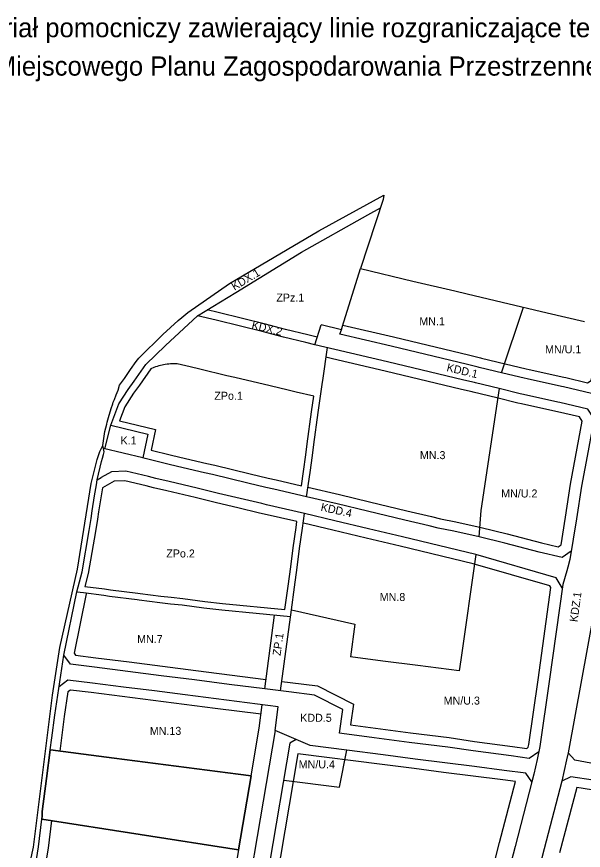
# Model space of a CAD drawing. Extents: x 7416945 to 7418410, y 5548550 to 5549803.
# Drawn here: x 7417259 to 7417613, y 5549282 to 5549803 of the extents above; entities that cross this region are included whole.
import ezdxf

# ---------------------------------------------------------------- set-up
doc = ezdxf.new("R2010")
doc.units = 0
for name, color, linetype in [('info', 7, 'Continuous'), ('linie rozgraniczające', 7, 'Continuous'), ('nieprzekraczalna linia lokalizacyjna', 7, 'Continuous'), ('nieprzekraczalne linie zabudowy', 7, 'Continuous'), ('przeznaczenia terenów', 7, 'Continuous'), ('wyrok sądu', 7, 'Continuous')]:
    doc.layers.add(name, color=color, linetype=linetype)

msp = doc.modelspace()

# ---------------------------------------------------------------- linework, layer by layer
at = {"layer": 'linie rozgraniczające'}
for p, q in [((7417562.21, 5549580.39), (7417575.91, 5549621.36)), ((7417430.79, 5549432.26), (7417470.53, 5549423.27)), ((7417460.95, 5549321.35), (7417465.4, 5549344.5)), ((7417397.8, 5549282.3), (7417274.82, 5549301.52))]:
    msp.add_line(p, q, dxfattribs=at)
for points in [[(7417265.78, 5549266.8), (7417269.56, 5549284.01), (7417281.43, 5549378.96), (7417286.09, 5549408.66), (7417297.04, 5549457.57), (7417305.73, 5549511.21), (7417309.41, 5549526.27), (7417310.95, 5549531.1), (7417312.91, 5549534.86), (7417314.25, 5549543.78), (7417315.36, 5549548.22), (7417315.7, 5549549.58), (7417316.52, 5549552.39), (7417318.21, 5549558.03), (7417319.09, 5549560.93), (7417319.48, 5549561.95), (7417320.14, 5549563.73), (7417321.28, 5549566.59), (7417322.44, 5549569.46), (7417323.3, 5549572.65), (7417326.48, 5549576.82), (7417326.92, 5549577.4), (7417328.51, 5549579.88), (7417330.15, 5549582.39), (7417333.79, 5549587.38), (7417335.36, 5549589.45), (7417340.1, 5549594.15), (7417345.97, 5549599.85), (7417346.5, 5549600.36), (7417350.44, 5549604.33), (7417359.93, 5549613.06), (7417362.31, 5549614.95), (7417366.04, 5549617.94), (7417392.12, 5549636.23), (7417447.88, 5549669.14), (7417488.65, 5549691.32), (7417488.23, 5549688.73), (7417473.96, 5549645.47), (7417506.75, 5549637.72), (7417506.75, 5549637.72), (7417533.04, 5549631.5), (7417540.76, 5549629.67), (7417562.48, 5549624.53), (7417590.76, 5549617.84), (7417614.12, 5549612.32)], [(7417314.25, 5549532.81), (7417317.93, 5549547.59), (7417323, 5549560.99), (7417328.79, 5549569.95), (7417332.54, 5549575.05), (7417339.88, 5549585.49), (7417352.08, 5549597.47), (7417372.07, 5549616.05), (7417396.1, 5549630.57), (7417437.07, 5549655.8), (7417478.59, 5549679.02), (7417486.4, 5549683.36), (7417486.46, 5549683.37)], [(7417462.02, 5549607.14), (7417462.8, 5549609.42), (7417473.96, 5549645.47)], [(7417446.94, 5549602.62), (7417441.05, 5549604.07), (7417427.15, 5549607.51), (7417413.7, 5549610.97), (7417400.22, 5549614.35), (7417384.97, 5549618.11), (7417378.17, 5549619.73)], [(7417445.43, 5549597.84), (7417439.85, 5549599.22), (7417425.93, 5549602.66), (7417412.47, 5549606.12), (7417399.01, 5549609.5), (7417383.79, 5549613.25), (7417372.07, 5549616.05)], [(7417619.99, 5549551.6), (7417616.03, 5549557.7), (7417598.58, 5549561.83), (7417597.44, 5549562.11), (7417575.89, 5549566.8), (7417573.85, 5549567.3), (7417560.72, 5549570.46), (7417545.86, 5549574.04), (7417545.19, 5549574.21), (7417538.59, 5549575.77), (7417490.83, 5549587.31), (7417457.88, 5549595), (7417445.43, 5549597.84), (7417449.35, 5549610.27)], [(7417624.4, 5549571.14), (7417618.37, 5549567.42), (7417600.92, 5549571.55), (7417599.7, 5549571.85), (7417578.14, 5549576.54), (7417576.21, 5549577.02), (7417563.06, 5549580.18), (7417548.26, 5549583.75), (7417547.57, 5549583.92), (7417540.91, 5549585.5), (7417493.14, 5549597.04), (7417461.13, 5549604.52), (7417462.02, 5549607.14), (7417449.35, 5549610.27)], [(7417633.2, 5549607.8), (7417620.9, 5549556.55), (7417616.31, 5549531.69), (7417612.22, 5549509.52), (7417608.98, 5549489.09), (7417604.95, 5549463.66), (7417603.56, 5549458.92), (7417602.9, 5549456.68), (7417600.38, 5549448.11)], [(7417652.74, 5549603.16), (7417639.38, 5549551.6), (7417635.56, 5549527.28), (7417631.94, 5549504.23), (7417628.25, 5549481.74), (7417626.38, 5549470.4), (7417624.29, 5549457.71), (7417624.07, 5549456.36), (7417624.04, 5549453.54), (7417603.72, 5549342.84), (7417602.77, 5549338.52), (7417599.85, 5549325.25), (7417588.8, 5549282.89), (7417582.37, 5549257.96)], [(7417453.1, 5549596.09), (7417450.22, 5549575.53), (7417450.07, 5549574.49), (7417447.41, 5549555.47), (7417444.62, 5549535.51), (7417443.69, 5549528.59), (7417442.28, 5549518.05), (7417440.12, 5549502.96)], [(7417560.72, 5549570.46), (7417549.3, 5549494.38), (7417547.88, 5549477.91)], [(7417317.93, 5549547.59), (7417341.07, 5549541.95), (7417337.98, 5549527.14)], [(7417309.48, 5549513.44), (7417311.99, 5549524.92), (7417312.62, 5549527.01), (7417313.29, 5549529.28), (7417313.78, 5549530.94), (7417313.31, 5549533.03)], [(7417605.77, 5549468.82), (7417600.1, 5549464.98), (7417585.77, 5549468.23), (7417564.26, 5549474), (7417548.09, 5549477.86), (7417532.26, 5549481.4), (7417522.63, 5549483.31), (7417517.01, 5549484.68), (7417501.66, 5549488.2), (7417478.3, 5549493.85), (7417459.39, 5549498.45), (7417440.17, 5549502.95), (7417419.85, 5549507.62), (7417414.85, 5549508.78), (7417403.59, 5549511.47), (7417381.46, 5549516.73), (7417376.48, 5549517.91), (7417359.56, 5549521.88), (7417353.59, 5549523.34), (7417339.47, 5549526.78), (7417337.98, 5549527.14), (7417313.31, 5549533.03), (7417312.91, 5549534.86)], [(7417600.08, 5549446.02), (7417596.4, 5549452.3), (7417546, 5549466.89), (7417500.15, 5549477.77), (7417478.89, 5549482.9), (7417458.04, 5549487.97), (7417438.91, 5549492.46), (7417415.18, 5549497.92), (7417412.28, 5549498.6), (7417398.75, 5549501.83), (7417385.32, 5549505.02), (7417371.92, 5549508.2), (7417354.31, 5549512.35), (7417345.97, 5549514.39), (7417341.45, 5549515.49), (7417327.34, 5549518.89), (7417318.33, 5549518.54), (7417311.85, 5549514.84)], [(7417270.81, 5549272.22), (7417272.81, 5549284.16), (7417274.82, 5549301.52), (7417275.05, 5549303.54), (7417274.98, 5549306.2), (7417277.78, 5549326.79), (7417280, 5549344.84), (7417280.95, 5549352.19), (7417282.87, 5549366.52), (7417288.51, 5549403.85), (7417296.68, 5549443.54), (7417299.91, 5549455.9), (7417304.38, 5549481.89), (7417305.56, 5549489.4), (7417306.21, 5549494.08), (7417307.79, 5549503.52), (7417308.95, 5549510.45), (7417309.48, 5549513.44), (7417311.85, 5549514.84)], [(7417424.03, 5549381.63), (7417430.79, 5549432.26), (7417432.7, 5549446.43), (7417434.35, 5549458.61), (7417435.96, 5549470.56), (7417437.66, 5549483.24), (7417438.91, 5549492.46)], [(7417546, 5549466.89), (7417536.78, 5549401.02), (7417535.75, 5549394.19)], [(7417600.38, 5549448.11), (7417591.9, 5549387.48), (7417586.15, 5549346.84), (7417584.38, 5549338.73), (7417582.4, 5549329.52), (7417581.1, 5549324.69), (7417570.58, 5549284.41), (7417563.36, 5549256.41)], [(7417296.68, 5549443.54), (7417300.86, 5549442.99), (7417313.48, 5549441.34), (7417317.1, 5549440.76), (7417334.32, 5549438.68), (7417335.7, 5549438.52), (7417348.63, 5549436.82), (7417355.16, 5549436.11), (7417362.48, 5549435.31), (7417376.12, 5549433.58), (7417387.21, 5549432.18), (7417430.22, 5549428.02)], [(7417414.1, 5549382.88), (7417420.26, 5549428.99)], [(7417470.53, 5549423.27), (7417467.67, 5549402.9)], [(7417585.45, 5549343.63), (7417579.42, 5549339.43), (7417568.13, 5549341.02), (7417544.48, 5549344.07), (7417528.56, 5549346.48), (7417504.4, 5549349.46), (7417482.53, 5549352.29), (7417462.37, 5549354.96), (7417460.97, 5549355.14), (7417463.05, 5549369.97), (7417445.24, 5549378.91), (7417429.2, 5549380.97), (7417414.1, 5549382.88), (7417391.84, 5549385.7), (7417370.32, 5549388.43), (7417349.39, 5549391.1), (7417328.55, 5549393.73), (7417307.72, 5549396.38), (7417292.62, 5549398.29), (7417288.51, 5549403.85)], [(7417535.75, 5549394.19), (7417509.8, 5549397.39), (7417487.93, 5549400.22), (7417467.67, 5549402.9)], [(7417581.1, 5549324.69), (7417577.44, 5549330.15), (7417563.73, 5549331.9), (7417545.24, 5549334.27), (7417526.74, 5549336.64), (7417508.25, 5549339.01), (7417488.26, 5549341.57), (7417465.4, 5549344.5), (7417442.59, 5549347.41), (7417420.61, 5549356.86), (7417422.52, 5549371.74), (7417403.17, 5549374.2), (7417383.83, 5549376.64), (7417364.49, 5549379.1), (7417345.14, 5549381.56), (7417325.8, 5549384.01), (7417306.45, 5549386.46), (7417291.08, 5549388.41), (7417285.55, 5549384.24)], [(7417405.66, 5549328.53), (7417410.72, 5549358.33), (7417412.6, 5549373)], [(7417420.61, 5549356.86), (7417394.15, 5549201.15), (7417385.15, 5549153.69), (7417379.31, 5549149.71)], [(7417433.7, 5549351.23), (7417429.92, 5549349.03), (7417404.45, 5549199.09), (7417395.47, 5549151.72), (7417399.45, 5549145.87)], [(7417280.18, 5549344.82), (7417300.77, 5549342.14), (7417320.11, 5549339.63), (7417339.45, 5549337.12), (7417358.78, 5549334.6), (7417378.12, 5549332.1), (7417397.46, 5549329.59), (7417405.66, 5549328.53)], [(7417906.81, 5549269.9), (7417851.87, 5549289.57), (7417833.76, 5549295.49), (7417808.87, 5549303.3), (7417795.71, 5549307.92), (7417790.77, 5549308.7), (7417775.81, 5549311.08), (7417756.77, 5549314.1), (7417742.03, 5549316.43), (7417726.22, 5549318.94), (7417710.69, 5549321.4), (7417699, 5549323.26), (7417679.25, 5549326.39), (7417661.44, 5549329.21), (7417642.3, 5549332.24), (7417632.4, 5549333.81), (7417607.94, 5549338.37), (7417603.72, 5549342.84)], [(7417405.66, 5549328.53), (7417397.8, 5549282.3)], [(7417425.99, 5549325.89), (7417460.95, 5549321.35)], [(7418147.34, 5549179.74), (7418143.99, 5549186.16), (7418084.45, 5549204.38), (7418040.68, 5549217.77), (7417983.92, 5549235), (7417952.55, 5549244.38), (7417903.8, 5549259.73), (7417872.26, 5549271.01), (7417847.4, 5549279.75), (7417826.56, 5549286.64), (7417807.47, 5549292.63), (7417790.03, 5549298.09), (7417775.67, 5549301.04), (7417764.12, 5549302.87), (7417752.53, 5549304.72), (7417740.93, 5549306.55), (7417719.26, 5549309.98), (7417700.5, 5549312.94), (7417681.74, 5549315.91), (7417662.97, 5549318.89), (7417638.22, 5549322.81), (7417619.42, 5549325.79), (7417605.57, 5549327.98), (7417599.85, 5549325.25)], [(7417397.8, 5549282.3), (7417396.12, 5549272.43), (7417384.31, 5549202.92), (7417374.39, 5549150.64)]]:
    msp.add_lwpolyline(points, dxfattribs=at)
at = {"layer": 'nieprzekraczalna linia lokalizacyjna'}
for points in [[(7417323.27, 5549550.41), (7417345.78, 5549544.92), (7417343.1, 5549532.07), (7417355.01, 5549529.17), (7417360.96, 5549527.71), (7417377.86, 5549523.75), (7417382.85, 5549522.57), (7417404.98, 5549517.31), (7417416.23, 5549514.62), (7417421.2, 5549513.47), (7417437.06, 5549509.82), (7417438.32, 5549518.6), (7417439.73, 5549529.12), (7417440.66, 5549536.05), (7417443.45, 5549556.02), (7417444.81, 5549565.76), (7417433.79, 5549568.29), (7417428.81, 5549569.44), (7417417.57, 5549572.13), (7417395.43, 5549577.39), (7417390.44, 5549578.57), (7417373.54, 5549582.54), (7417367.6, 5549583.99), (7417359.32, 5549586.01), (7417358.28, 5549586.04), (7417357.23, 5549586.04), (7417356.18, 5549586.01), (7417355.13, 5549585.95), (7417354.09, 5549585.86), (7417353.04, 5549585.74), (7417351.99, 5549585.59), (7417350.95, 5549585.4), (7417349.92, 5549585.19), (7417348.89, 5549584.95), (7417347.87, 5549584.68), (7417346.86, 5549584.37), (7417345.87, 5549584.04), (7417344.88, 5549583.69), (7417342.98, 5549582.93), (7417335.79, 5549572.72), (7417332.08, 5549567.68), (7417326.59, 5549559.18), (7417323.27, 5549550.41)], [(7417312.66, 5549508.4), (7417310.16, 5549493.47), (7417309.52, 5549488.81), (7417308.33, 5549481.24), (7417303.82, 5549455.05), (7417301.7, 5549446.91), (7417314.06, 5549445.3), (7417317.66, 5549444.72), (7417334.79, 5549442.65), (7417336.19, 5549442.49), (7417349.11, 5549440.79), (7417355.59, 5549440.09), (7417362.95, 5549439.28), (7417376.62, 5549437.55), (7417387.65, 5549436.16), (7417426.77, 5549432.38), (7417428.74, 5549446.97), (7417430.39, 5549459.15), (7417432, 5549471.09), (7417433.7, 5549483.77), (7417434.18, 5549487.39), (7417413.83, 5549492.08), (7417410.9, 5549492.76), (7417397.36, 5549495.99), (7417383.94, 5549499.18), (7417370.54, 5549502.36), (7417352.91, 5549506.52), (7417344.55, 5549508.56), (7417340.03, 5549509.66), (7417326.74, 5549512.86), (7417320.03, 5549512.6), (7417312.66, 5549508.4)]]:
    msp.add_lwpolyline(points, dxfattribs=at)
at = {"layer": 'nieprzekraczalne linie zabudowy'}
for points in [[(7417463.05, 5549610.23), (7417494.53, 5549602.88), (7417542.31, 5549591.33), (7417549, 5549589.75), (7417549.7, 5549589.57), (7417564.47, 5549586.02), (7417577.63, 5549582.85), (7417579.5, 5549582.39), (7417601.05, 5549577.7), (7417602.33, 5549577.38), (7417615.96, 5549574.16), (7417618.27, 5549575.58), (7417626.39, 5549609.41)], [(7417440.97, 5549508.92), (7417460.78, 5549504.28), (7417479.72, 5549499.68), (7417503.04, 5549494.04), (7417518.39, 5549490.52), (7417523.92, 5549489.17), (7417533.5, 5549487.27), (7417549.44, 5549483.71), (7417565.73, 5549479.82), (7417587.21, 5549474.06), (7417597.55, 5549471.71), (7417599.33, 5549472.91), (7417602.07, 5549490.19), (7417605.32, 5549510.7), (7417612.6, 5549550.13), (7417610.9, 5549552.75), (7417597.17, 5549556), (7417596.09, 5549556.26), (7417574.54, 5549560.95), (7417572.43, 5549561.47), (7417559.32, 5549564.63), (7417544.42, 5549568.22), (7417543.76, 5549568.38), (7417537.2, 5549569.93), (7417489.44, 5549581.47), (7417456.53, 5549589.15), (7417452.26, 5549590.13)], [(7417424.82, 5549387.57), (7417429.96, 5549386.92), (7417447.02, 5549384.73), (7417469.59, 5549373.4), (7417467.75, 5549360.3), (7417483.31, 5549358.24), (7417505.15, 5549355.41), (7417529.38, 5549352.42), (7417545.31, 5549350.01), (7417568.93, 5549346.96), (7417577.92, 5549345.7), (7417578.88, 5549346.37), (7417579.26, 5549348.08), (7417584.96, 5549388.45), (7417593.04, 5549446.17), (7417592.43, 5549447.2), (7417544.48, 5549461.09), (7417498.75, 5549471.94), (7417477.48, 5549477.07), (7417456.64, 5549482.14), (7417438.35, 5549486.43)], [(7417302.68, 5549442.75), (7417302.52, 5549442.18), (7417294.93, 5549405.26), (7417295.92, 5549403.92), (7417308.48, 5549402.33), (7417329.3, 5549399.68), (7417350.15, 5549397.05), (7417371.08, 5549394.38), (7417414.9, 5549388.82)], [(7417411.84, 5549367.06), (7417383.08, 5549370.69), (7417363.73, 5549373.15), (7417344.38, 5549375.61), (7417325.05, 5549378.06), (7417305.7, 5549380.51), (7417292.74, 5549382.15), (7417291.11, 5549380.92), (7417288.81, 5549365.7), (7417286.13, 5549344.04)], [(7417434.88, 5549342.36), (7417410.35, 5549198.03), (7417401.82, 5549153.05), (7417403.01, 5549151.3), (7417404.99, 5549150.92), (7417424.63, 5549147.18), (7417444.28, 5549143.47), (7417463.93, 5549139.73), (7417483.57, 5549135.98), (7417503.23, 5549132.27), (7417519.62, 5549129.16), (7417523.72, 5549144.71), (7417528.82, 5549164.11), (7417533.94, 5549183.53), (7417553.08, 5549256.59), (7417560.91, 5549286.92), (7417570.83, 5549324.94), (7417562.97, 5549325.95), (7417544.48, 5549328.32), (7417525.98, 5549330.69), (7417507.49, 5549333.06), (7417487.5, 5549335.62), (7417434.88, 5549342.36)], [(7417824.72, 5549280.93), (7417805.68, 5549286.9), (7417788.53, 5549292.27), (7417774.6, 5549295.14), (7417763.18, 5549296.94), (7417751.59, 5549298.79), (7417739.99, 5549300.62), (7417718.32, 5549304.05), (7417699.56, 5549307.01), (7417680.8, 5549309.98), (7417662.03, 5549312.96), (7417637.28, 5549316.88), (7417618.48, 5549319.86), (7417609.16, 5549321.34), (7417598.48, 5549280.38)], [(7417280.75, 5549300.59), (7417278.75, 5549283.32), (7417276.73, 5549271.22), (7417267.63, 5549218.08), (7417264.16, 5549195.55), (7417262.15, 5549179.79), (7417263.67, 5549177.71), (7417287.09, 5549173.26), (7417326.39, 5549165.83), (7417346.03, 5549162.1), (7417365.68, 5549158.4), (7417375.51, 5549156.54)]]:
    msp.add_lwpolyline(points, dxfattribs=at)
at = {"layer": 'wyrok sądu'}
for p, q in [((7417280.18, 5549344.82), (7417280, 5549344.84)), ((7417300.77, 5549342.14), (7417280.18, 5549344.82)), ((7417320.11, 5549339.63), (7417300.77, 5549342.14)), ((7417339.45, 5549337.12), (7417320.11, 5549339.63)), ((7417358.78, 5549334.6), (7417339.45, 5549337.12)), ((7417378.12, 5549332.1), (7417358.78, 5549334.6)), ((7417397.46, 5549329.59), (7417378.12, 5549332.1)), ((7417405.66, 5549328.53), (7417397.46, 5549329.59)), ((7417397.8, 5549282.3), (7417405.66, 5549328.53)), ((7417274.98, 5549306.2), (7417275.05, 5549303.54))]:
    msp.add_line(p, q, dxfattribs=at)
for points in [[(7417280, 5549344.84), (7417277.78, 5549326.79), (7417274.98, 5549306.2)], [(7417275.05, 5549303.54), (7417274.82, 5549301.52), (7417397.8, 5549282.3)]]:
    msp.add_lwpolyline(points, dxfattribs=at)

# ---------------------------------------------------------------- texts
at = {"layer": 'info'}
for s, p in [('Materiał pomocniczy zawierający linie rozgraniczające teren o różnym przeznaczeniu i różnych warunkach zagospodarowania terenu, ', (7417215.4, 5549790.04)), ('opracowane w skali 1:1000 pochodzące z Miejscowego Planu Zagospodarowania Przestrzennego obszaru "Rejon ulic Podłużnej i Pylnej" zatwierdzonego uchwałą RMK Nr VII/120/19 z dnia 13 lutego 2019 r.', (7416943.86, 5549766.04))]:
    msp.add_text(s, height=12, dxfattribs=at).set_placement(p)
at = {"layer": 'przeznaczenia terenów'}
for s, rotation, p in [('KDX.1', 30.9582, (7417395.2, 5549631.63)), ('KDX.2', 346.19, (7417405.6, 5549608.06)), ('KDD.1', 346.6025, (7417527.52, 5549581.51)), ('KDD.4', 347.4696, (7417448.82, 5549494.26)), ('KDZ.1', 82.101, (7417609.59, 5549424.4)), ('ZP.1', 81.7625, (7417423.94, 5549403.41))]:
    msp.add_text(s, height=5, rotation=rotation, dxfattribs=at).set_placement(p)
for s, p in [('ZPz.1', (7417421.38, 5549624.85)), ('MN.1', (7417510.75, 5549610.07)), ('MN/U.1', (7417589.36, 5549592.56)), ('ZPo.1', (7417382.63, 5549563.51)), ('K.1', (7417323.98, 5549535.58)), ('MN.3', (7417511.11, 5549526.42)), ('MN/U.2', (7417561.92, 5549502.47)), ('ZPo.2', (7417352.58, 5549464.97)), ('MN.8', (7417486.01, 5549437.77)), ('MN.7', (7417334.36, 5549411.52)), ('MN/U.3', (7417525.97, 5549373.05)), ('KDD.5', (7417436.31, 5549362.3)), ('MN.13', (7417342.27, 5549354.13)), ('MN/U.4', (7417435.36, 5549333.19))]:
    msp.add_text(s, height=5, dxfattribs=at).set_placement(p)

doc.saveas('drawing.dxf')
